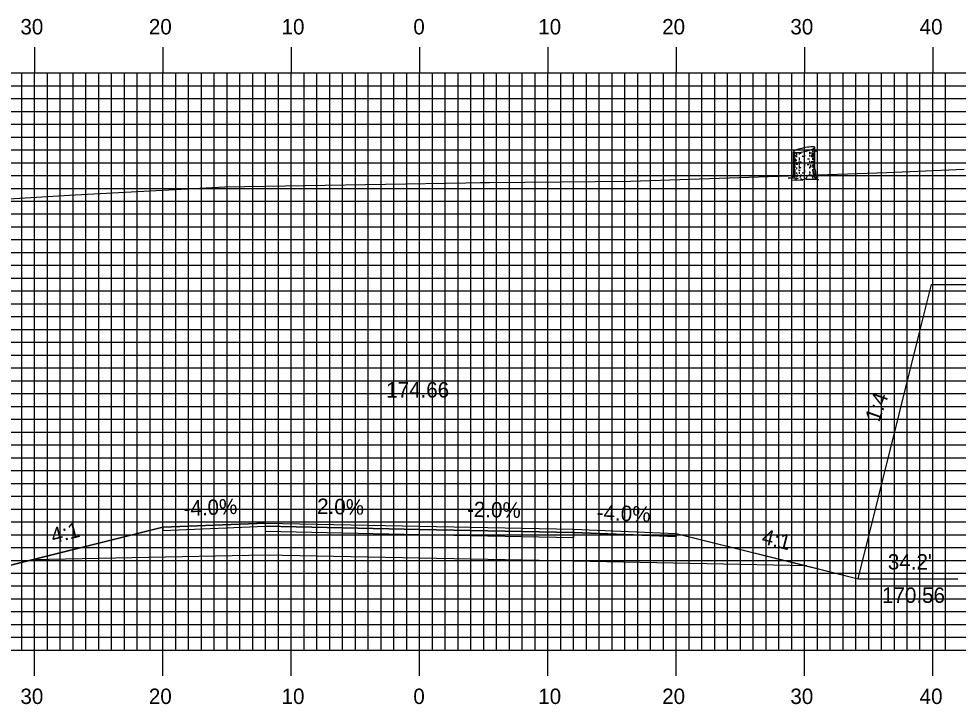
# Model space of a CAD drawing. Extents: x 1795240 to 1795583, y 442591 to 442811.
# Drawn here: x 1795374.1 to 1795447.3, y 442679.4 to 442732.9 of the extents above; entities that cross this region are included whole.
import ezdxf

# ---------------------------------------------------------------- set-up
doc = ezdxf.new("R2010")
doc.units = 0
for name, color, linetype in [('ANNOTATION', 7, 'Continuous'), ('D_Roadway_Centerline', 7, 'Continuous'), ('D_Roadway_Centerline_Text', 7, 'Continuous'), ('D_Roadway_Edge_Shoulder', 7, 'Continuous'), ('D_Roadway_Edge_TW', 7, 'Continuous'), ('D_Roadway_Pavement', 7, 'Continuous'), ('D_Roadway_SlopeLines', 7, 'Continuous'), ('D_Roadway_SubGrade', 7, 'Continuous'), ('H_V ANNOTATION', 7, 'Continuous'), ('M_Trees_Conifer_Pay', 7, 'Continuous'), ('MAJOR', 7, 'Continuous'), ('MINOR', 7, 'Continuous'), ('PDRAIN', 7, 'Continuous'), ('S_Roadway_Centerline', 7, 'Continuous')]:
    doc.layers.add(name, color=color, linetype=linetype)

msp = doc.modelspace()

# ---------------------------------------------------------------- linework, layer by layer
at = {"layer": 'D_Roadway_Centerline'}
msp.add_lwpolyline([(1795337.256, 442715.538), (1795361.802, 442703.265), (1795367.802, 442703.265), (1795371.192, 442689.704), (1795375.192, 442690.704), (1795385.366, 442693.248), (1795393.366, 442693.568), (1795405.366, 442693.328), (1795417.366, 442693.088), (1795425.366, 442692.768), (1795435.54, 442690.224), (1795439.54, 442689.224), (1795444.366, 442708.528)], dxfattribs=at)
at = {"layer": 'D_Roadway_Edge_Shoulder'}
for points in [[(1795393.366, 442693.568), (1795385.366, 442693.248), (1795385.366, 442692.998), (1795393.366, 442693.318)], [(1795417.366, 442693.088), (1795425.366, 442692.768), (1795425.366, 442692.518), (1795417.366, 442692.838)]]:
    msp.add_lwpolyline(points, close=True, dxfattribs=at)
at = {"layer": 'D_Roadway_Edge_TW'}
msp.add_lwpolyline([(1795393.366, 442693.318), (1795393.366, 442693.568), (1795405.366, 442693.328), (1795417.366, 442693.088), (1795417.366, 442692.838), (1795405.366, 442693.078)], close=True, dxfattribs=at)
at = {"layer": 'D_Roadway_Pavement'}
msp.add_lwpolyline([(1795393.366, 442692.901), (1795393.366, 442693.318), (1795405.366, 442693.078), (1795417.366, 442692.838), (1795417.366, 442692.421), (1795405.366, 442692.661)], close=True, dxfattribs=at)
at = {"layer": 'D_Roadway_SlopeLines'}
for points in [[(1795444.366, 442708.528), (1795445.275, 442712.165), (1795451.275, 442712.165)], [(1795385.366, 442693.248), (1795371.192, 442689.704)], [(1795425.366, 442692.768), (1795439.54, 442689.224)]]:
    msp.add_lwpolyline(points, dxfattribs=at)
at = {"layer": 'D_Roadway_SubGrade'}
msp.add_lwpolyline([(1795393.366, 442691.068), (1795375.192, 442690.704), (1795385.366, 442693.248), (1795385.366, 442692.998), (1795393.366, 442693.318), (1795405.366, 442693.078), (1795417.366, 442692.838), (1795425.366, 442692.518), (1795425.366, 442692.768), (1795435.54, 442690.224), (1795417.366, 442690.588), (1795405.366, 442690.828)], close=True, dxfattribs=at)
at = {"layer": 'M_Trees_Conifer_Pay'}
for p, q in [((1795434.504, 442720.788), (1795434.504, 442722.51)), ((1795434.551, 442722.472), (1795434.551, 442722.001)), ((1795434.609, 442722.461), (1795434.609, 442722.363)), ((1795434.609, 442722.289), (1795434.609, 442722.085)), ((1795434.735, 442722.453), (1795434.735, 442722.221)), ((1795434.735, 442722.18), (1795434.735, 442722.106)), ((1795434.954, 442722.474), (1795434.954, 442722.306)), ((1795435.36, 442722.242), (1795435.36, 442722.147)), ((1795435.75, 442722.516), (1795435.75, 442722.316)), ((1795435.75, 442722.258), (1795435.75, 442722.17)), ((1795435.979, 442722.712), (1795435.979, 442722.489)), ((1795435.979, 442722.4), (1795435.979, 442722.353)), ((1795436.036, 442722.217), (1795435.985, 442722.157)), ((1795436.096, 442722.773), (1795436.096, 442722.61)), ((1795436.096, 442722.542), (1795436.096, 442722.414)), ((1795436.096, 442722.227), (1795436.096, 442721.891)), ((1795436.168, 442721.198), (1795436.168, 442722.845)), ((1795434.551, 442721.937), (1795434.551, 442721.628)), ((1795434.551, 442721.581), (1795434.551, 442721.089)), ((1795434.609, 442722.027), (1795434.609, 442721.828)), ((1795434.609, 442721.781), (1795434.609, 442721.445)), ((1795434.735, 442721.703), (1795434.735, 442721.564)), ((1795434.954, 442722.069), (1795434.954, 442721.832)), ((1795434.954, 442721.587), (1795434.954, 442721.435)), ((1795435.36, 442721.628), (1795435.36, 442721.554)), ((1795435.36, 442721.529), (1795435.36, 442721.381)), ((1795435.75, 442721.822), (1795435.75, 442721.717)), ((1795435.979, 442722.017), (1795435.979, 442721.886)), ((1795435.979, 442721.775), (1795435.979, 442721.665)), ((1795435.979, 442721.529), (1795435.979, 442721.388)), ((1795436.096, 442721.855), (1795436.096, 442721.692)), ((1795436.096, 442721.645), (1795436.096, 442721.428)), ((1795434.551, 442721.035), (1795434.551, 442720.788)), ((1795434.609, 442721.391), (1795434.609, 442721.256)), ((1795434.609, 442721.157), (1795434.609, 442720.778)), ((1795434.735, 442721.292), (1795434.735, 442721.151)), ((1795434.735, 442720.889), (1795434.735, 442720.794)), ((1795434.954, 442721.391), (1795434.954, 442721.218)), ((1795434.954, 442720.941), (1795434.954, 442720.788)), ((1795435.36, 442721.089), (1795435.36, 442720.936)), ((1795435.75, 442721.35), (1795435.75, 442721.204)), ((1795435.75, 442720.972), (1795435.75, 442720.883)), ((1795435.979, 442721.161), (1795435.979, 442720.988)), ((1795436.096, 442721.397), (1795436.096, 442721.323)), ((1795436.096, 442721.283), (1795436.096, 442721.109)), ((1795434.735, 442720.395), (1795434.897, 442720.458)), ((1795435.172, 442720.33), (1795435.046, 442720.395))]:
    msp.add_line(p, q, dxfattribs=at)
for points in [[(1795435.951, 442722.306), (1795435.92, 442722.221), (1795435.916, 442722.153), (1795435.947, 442722.09)], [(1795435.985, 442722.343), (1795436.021, 442722.269), (1795436.069, 442722.326), (1795436.126, 442722.394), (1795436.219, 442722.588), (1795436.283, 442722.635), (1795436.314, 442722.641)], [(1795435.999, 442722.09), (1795436.036, 442722.217), (1795436.099, 442722.332), (1795436.13, 442722.4), (1795436.199, 442722.546)], [(1795436.214, 442722.576), (1795436.289, 442722.584), (1795436.361, 442722.485)], [(1795434.683, 442721.815), (1795434.677, 442721.911), (1795434.72, 442721.888), (1795434.72, 442721.793)], [(1795435.822, 442721.416), (1795435.834, 442721.34), (1795435.882, 442721.35), (1795435.869, 442721.517)], [(1795436.168, 442721.198), (1795436.219, 442720.936), (1795436.235, 442720.662), (1795436.293, 442720.537), (1795436.429, 442720.506), (1795436.198, 442720.469), (1795436.198, 442720.469), (1795436.204, 442720.422), (1795436.452, 442720.327), (1795436.177, 442720.344), (1795435.822, 442720.364), (1795435.5, 442720.353), (1795435.507, 442720.436), (1795435.359, 442720.353), (1795435.172, 442720.33), (1795435.196, 442720.263), (1795434.928, 442720.306), (1795434.708, 442720.279), (1795434.415, 442720.296), (1795434.704, 442720.353), (1795434.735, 442720.395), (1795434.572, 442720.453), (1795434.335, 442720.463), (1795434.094, 442720.463), (1795434.436, 442720.521), (1795434.477, 442720.601), (1795434.504, 442720.788)], [(1795434.551, 442720.741), (1795434.53, 442720.662), (1795434.51, 442720.568)], [(1795434.63, 442720.72), (1795434.635, 442720.605), (1795434.582, 442720.516), (1795434.572, 442720.453)], [(1795434.792, 442720.747), (1795434.792, 442720.615), (1795434.704, 442720.516)], [(1795435.019, 442720.506), (1795435.086, 442720.601), (1795435.113, 442720.741)], [(1795435.758, 442720.805), (1795435.768, 442720.679), (1795435.842, 442720.636)], [(1795435.994, 442720.91), (1795436.069, 442720.805), (1795436.073, 442720.632), (1795436.198, 442720.469)], [(1795436.093, 442721.056), (1795436.099, 442720.91), (1795436.147, 442720.842), (1795436.157, 442720.642)], [(1795435.507, 442720.436), (1795435.581, 442720.578), (1795435.591, 442720.679)], [(1795436.036, 442720.416), (1795436.021, 442720.554), (1795435.947, 442720.683)]]:
    msp.add_lwpolyline(points, dxfattribs=at)
for centre, radius, start, end in [((1795434.536, 442722.331), 0.0334, 163.94846, 180), ((1795434.536, 442722.331), 0.0334, 180, 196.05154), ((1795434.535, 442722.508), 0.0314, 156.51582, 169.2194), ((1795434.53, 442722.509), 0.0264, 169.2194, 180.03145), ((1795434.526, 442722.509), 0.0226, 180.03145, 191.7194), ((1795434.526, 442722.509), 0.0226, 191.7194, 203.40735), ((1795434.546, 442722.334), 0.0441, 196.05154, 210), ((1795434.555, 442722.5), 0.0527, 146.7194, 156.51582), ((1795434.53, 442722.511), 0.0264, 203.40735, 214.2194), ((1795434.534, 442722.514), 0.0314, 214.2194, 226.92298), ((1795434.562, 442722.343), 0.0624, 210, 228.74941), ((1795434.579, 442722.484), 0.0817, 132.38868, 146.7194), ((1795434.548, 442722.529), 0.0527, 226.92298, 236.7194), ((1795434.564, 442722.553), 0.0817, 236.7194, 251.05013), ((1795434.634, 442722.426), 0.172, 228.74941, 240), ((1795434.693, 442722.359), 0.251, 124.2194, 132.38868), ((1795434.619, 442722.713), 0.251, 251.05013, 259.2194), ((1795434.834, 442722.771), 0.571, 240, 240.33672), ((1795435.003, 442721.904), 0.802, 108.05939, 124.2194), ((1795434.722, 442723.254), 0.802, 259.2194, 275.37941), ((1795434.834, 442722.771), 0.571, 246.85973, 257.98457), ((1795436.359, 442717.742), 5.179, 101.7194, 108.05939), ((1795434.312, 442727.612), 5.179, 275.37941, 281.7194), ((1795435.336, 442726.522), 4.124, 264.6955, 266.73309), ((1795436.359, 442717.742), 5.179, 95.37941, 101.7194), ((1795434.312, 442727.612), 5.179, 281.7194, 288.05939), ((1795435.334, 442726.289), 4.124, 275.78493, 277.05584), ((1795435.336, 442726.522), 4.124, 276.23804, 278.1032), ((1795435.949, 442722.1), 0.802, 79.2194, 95.37941), ((1795435.669, 442723.451), 0.802, 288.05939, 304.2194), ((1795435.837, 442723.004), 0.571, 278.1032, 284.36665), ((1795435.837, 442723.158), 0.571, 284.43166, 292.41325), ((1795435.837, 442723.004), 0.571, 297.0237, 300), ((1795436.052, 442722.641), 0.251, 71.05013, 79.2194), ((1795435.979, 442722.995), 0.251, 304.2194, 312.38868), ((1795436.036, 442722.813), 0.172, 300, 311.25059), ((1795436.036, 442722.659), 0.172, 300, 311.25059), ((1795436.107, 442722.801), 0.0817, 56.7194, 71.05013), ((1795436.093, 442722.87), 0.0817, 312.38868, 326.7194), ((1795436.108, 442722.731), 0.0624, 311.25059, 330), ((1795436.108, 442722.576), 0.0624, 311.25059, 330), ((1795436.123, 442722.825), 0.0527, 46.92298, 56.7194), ((1795436.137, 442722.841), 0.0314, 34.2194, 46.92298), ((1795436.117, 442722.855), 0.0527, 326.7194, 336.51582), ((1795436.124, 442722.722), 0.0441, 330, 343.94846), ((1795436.124, 442722.567), 0.0441, 330, 343.94846), ((1795436.142, 442722.844), 0.0264, 23.40735, 34.2194), ((1795436.136, 442722.846), 0.0314, 336.51582, 349.2194), ((1795436.145, 442722.845), 0.0226, 11.7194, 23.40735), ((1795436.145, 442722.845), 0.0226, 0.03145, 11.7194), ((1795436.141, 442722.845), 0.0264, 349.2194, 0.03145), ((1795436.135, 442722.719), 0.0334, 343.94846, 354.21506), ((1795436.135, 442722.564), 0.0334, 343.94846, 354.21506), ((1795434.536, 442721.885), 0.0334, 163.94846, 180), ((1795434.536, 442721.885), 0.0334, 180, 196.05154), ((1795434.536, 442721.675), 0.0334, 163.94846, 180), ((1795434.536, 442721.675), 0.0334, 180, 196.05154), ((1795434.546, 442721.888), 0.0441, 196.05154, 210), ((1795434.546, 442721.677), 0.0441, 196.05154, 210), ((1795434.562, 442721.897), 0.0624, 210, 228.74941), ((1795434.562, 442721.687), 0.0624, 210, 228.74941), ((1795434.634, 442721.979), 0.172, 228.74941, 240), ((1795434.634, 442721.769), 0.172, 228.74941, 240), ((1795434.834, 442722.324), 0.571, 240, 240.33672), ((1795434.834, 442722.114), 0.571, 240, 246.85973), ((1795434.835, 442722.56), 0.571, 240, 247.05866), ((1795434.834, 442722.114), 0.571, 259.27072, 261.8968), ((1795435.334, 442725.632), 4.124, 261.8968, 263.14738), ((1795435.334, 442725.842), 4.124, 264.08098, 266.66759), ((1795435.334, 442726.289), 4.124, 268.07512, 270), ((1795435.334, 442726.289), 4.124, 270, 270.35814), ((1795435.334, 442725.632), 4.124, 270, 270.35814), ((1795435.334, 442725.632), 4.124, 273.14934, 275.45691), ((1795435.336, 442726.078), 4.124, 273.70524, 275.95043), ((1795435.334, 442725.842), 4.124, 277.61247, 278.1032), ((1795435.835, 442722.324), 0.571, 278.1032, 286.92962), ((1795435.837, 442722.56), 0.571, 284.44928, 297.04285), ((1795435.835, 442722.324), 0.571, 297.18959, 300), ((1795435.835, 442722.114), 0.571, 297.18959, 300), ((1795436.034, 442721.979), 0.172, 300, 311.25059), ((1795436.034, 442721.769), 0.172, 300, 311.25059), ((1795436.107, 442721.897), 0.0624, 311.25059, 330), ((1795436.107, 442721.687), 0.0624, 311.25059, 330), ((1795436.123, 442721.888), 0.0441, 330, 343.94846), ((1795436.123, 442721.677), 0.0441, 330, 343.94846), ((1795436.133, 442721.885), 0.0334, 343.94846, 354.21506), ((1795436.133, 442721.675), 0.0334, 343.94846, 354.21506), ((1795436.134, 442722.12), 0.0334, 343.94846, 354.21506), ((1795434.536, 442721.438), 0.0334, 163.94846, 180), ((1795434.536, 442721.438), 0.0334, 180, 196.05154), ((1795434.536, 442721.24), 0.0334, 163.94846, 180), ((1795434.536, 442721.044), 0.0334, 163.94846, 180), ((1795434.536, 442721.044), 0.0334, 180, 196.05154), ((1795434.536, 442720.824), 0.0334, 163.94846, 180), ((1795434.536, 442720.824), 0.0334, 180, 196.05154), ((1795434.546, 442721.441), 0.0441, 196.05154, 210), ((1795434.546, 442721.047), 0.0441, 196.05154, 210), ((1795434.546, 442720.827), 0.0441, 196.05154, 210), ((1795434.562, 442721.45), 0.0624, 210, 228.74941), ((1795434.562, 442721.057), 0.0624, 210, 228.74941), ((1795434.562, 442720.836), 0.0624, 210, 228.74941), ((1795434.634, 442721.532), 0.172, 228.74941, 240), ((1795434.634, 442721.139), 0.172, 228.74941, 240), ((1795434.634, 442720.919), 0.172, 228.74941, 240), ((1795434.834, 442721.878), 0.571, 240, 246.85973), ((1795434.823, 442721.686), 0.571, 241.23686, 248.02677), ((1795434.834, 442721.484), 0.571, 240, 246.85973), ((1795434.834, 442721.264), 0.571, 240, 244.53138), ((1795435.334, 442725.197), 4.124, 263.49906, 265.83975), ((1795435.334, 442725.395), 4.124, 264.71603, 266.31934), ((1795435.334, 442725.002), 4.124, 267.81166, 270), ((1795435.334, 442725.002), 4.124, 270, 270.13279), ((1795435.334, 442725.002), 4.124, 275.78493, 276.78961), ((1795435.835, 442721.878), 0.571, 285.39827, 297.18959), ((1795435.835, 442721.484), 0.571, 288.50673, 297.27208), ((1795435.835, 442721.68), 0.571, 289.29072, 300), ((1795436.034, 442721.335), 0.172, 300, 311.25059), ((1795436.034, 442720.919), 0.172, 300, 311.25059), ((1795436.107, 442721.252), 0.0624, 311.25059, 330), ((1795436.107, 442720.836), 0.0624, 311.25059, 330), ((1795436.123, 442721.243), 0.0441, 330, 343.94846), ((1795436.123, 442720.827), 0.0441, 330, 343.94846), ((1795436.133, 442721.24), 0.0334, 343.94846, 354.21506), ((1795436.133, 442720.824), 0.0334, 343.94846, 354.21506), ((1795435.334, 442724.781), 4.124, 262.44379, 263.51202), ((1795435.334, 442724.781), 4.124, 277.36842, 278.1032), ((1795435.835, 442721.264), 0.571, 278.1032, 281.63703)]:
    msp.add_arc(centre, radius, start, end, dxfattribs=at)
at = {"layer": 'MAJOR'}
for p, q in [((1795375.366, 442730.669), (1795375.366, 442728.665)), ((1795385.366, 442730.669), (1795385.366, 442728.665)), ((1795395.366, 442730.669), (1795395.366, 442728.665)), ((1795405.366, 442730.669), (1795405.366, 442728.665)), ((1795415.366, 442730.669), (1795415.366, 442728.665)), ((1795425.366, 442730.669), (1795425.366, 442728.665)), ((1795435.366, 442730.669), (1795435.366, 442728.665)), ((1795445.366, 442730.669), (1795445.366, 442728.665)), ((1795265.366, 442728.665), (1795545.366, 442728.665)), ((1795265.366, 442728.665), (1795545.366, 442728.665)), ((1795375.366, 442683.665), (1795375.366, 442728.665)), ((1795385.366, 442683.665), (1795385.366, 442728.665)), ((1795395.366, 442683.665), (1795395.366, 442728.665)), ((1795405.366, 442683.665), (1795405.366, 442728.665)), ((1795415.366, 442683.665), (1795415.366, 442728.665)), ((1795425.366, 442683.665), (1795425.366, 442728.665)), ((1795435.366, 442683.665), (1795435.366, 442728.665)), ((1795445.366, 442683.665), (1795445.366, 442728.665)), ((1795265.366, 442723.665), (1795545.366, 442723.665)), ((1795265.366, 442718.665), (1795545.366, 442718.665)), ((1795265.366, 442713.665), (1795545.366, 442713.665)), ((1795265.366, 442708.665), (1795545.366, 442708.665)), ((1795265.366, 442703.665), (1795545.366, 442703.665)), ((1795265.366, 442698.665), (1795545.366, 442698.665)), ((1795265.366, 442693.665), (1795545.366, 442693.665)), ((1795265.366, 442688.665), (1795545.366, 442688.665)), ((1795265.366, 442683.665), (1795545.366, 442683.665)), ((1795265.366, 442683.665), (1795545.366, 442683.665)), ((1795375.366, 442681.661), (1795375.366, 442683.665)), ((1795385.366, 442681.661), (1795385.366, 442683.665)), ((1795395.366, 442681.661), (1795395.366, 442683.665)), ((1795405.366, 442681.661), (1795405.366, 442683.665)), ((1795415.366, 442681.661), (1795415.366, 442683.665)), ((1795425.366, 442681.661), (1795425.366, 442683.665)), ((1795435.366, 442681.661), (1795435.366, 442683.665)), ((1795445.366, 442681.661), (1795445.366, 442683.665))]:
    msp.add_line(p, q, dxfattribs=at)
at = {"layer": 'MINOR'}
for p, q in [((1795374.366, 442683.665), (1795374.366, 442728.665)), ((1795376.366, 442683.665), (1795376.366, 442728.665)), ((1795377.366, 442683.665), (1795377.366, 442728.665)), ((1795378.366, 442683.665), (1795378.366, 442728.665)), ((1795379.366, 442683.665), (1795379.366, 442728.665)), ((1795380.366, 442683.665), (1795380.366, 442728.665)), ((1795381.366, 442683.665), (1795381.366, 442728.665)), ((1795382.366, 442683.665), (1795382.366, 442728.665)), ((1795383.366, 442683.665), (1795383.366, 442728.665)), ((1795384.366, 442683.665), (1795384.366, 442728.665)), ((1795386.366, 442683.665), (1795386.366, 442728.665)), ((1795387.366, 442683.665), (1795387.366, 442728.665)), ((1795388.366, 442683.665), (1795388.366, 442728.665)), ((1795389.366, 442683.665), (1795389.366, 442728.665)), ((1795390.366, 442683.665), (1795390.366, 442728.665)), ((1795391.366, 442683.665), (1795391.366, 442728.665)), ((1795392.366, 442683.665), (1795392.366, 442728.665)), ((1795393.366, 442683.665), (1795393.366, 442728.665)), ((1795394.366, 442683.665), (1795394.366, 442728.665)), ((1795396.366, 442683.665), (1795396.366, 442728.665)), ((1795397.366, 442683.665), (1795397.366, 442728.665)), ((1795398.366, 442683.665), (1795398.366, 442728.665)), ((1795399.366, 442683.665), (1795399.366, 442728.665)), ((1795400.366, 442683.665), (1795400.366, 442728.665)), ((1795401.366, 442683.665), (1795401.366, 442728.665)), ((1795402.366, 442683.665), (1795402.366, 442728.665)), ((1795403.366, 442683.665), (1795403.366, 442728.665)), ((1795404.366, 442683.665), (1795404.366, 442728.665)), ((1795406.366, 442683.665), (1795406.366, 442728.665)), ((1795407.366, 442683.665), (1795407.366, 442728.665)), ((1795408.366, 442683.665), (1795408.366, 442728.665)), ((1795409.366, 442683.665), (1795409.366, 442728.665)), ((1795410.366, 442683.665), (1795410.366, 442728.665)), ((1795411.366, 442683.665), (1795411.366, 442728.665)), ((1795412.366, 442683.665), (1795412.366, 442728.665)), ((1795413.366, 442683.665), (1795413.366, 442728.665)), ((1795414.366, 442683.665), (1795414.366, 442728.665)), ((1795416.366, 442683.665), (1795416.366, 442728.665)), ((1795417.366, 442683.665), (1795417.366, 442728.665)), ((1795418.366, 442683.665), (1795418.366, 442728.665)), ((1795419.366, 442683.665), (1795419.366, 442728.665)), ((1795420.366, 442683.665), (1795420.366, 442728.665)), ((1795421.366, 442683.665), (1795421.366, 442728.665)), ((1795422.366, 442683.665), (1795422.366, 442728.665)), ((1795423.366, 442683.665), (1795423.366, 442728.665)), ((1795424.366, 442683.665), (1795424.366, 442728.665)), ((1795426.366, 442683.665), (1795426.366, 442728.665)), ((1795427.366, 442683.665), (1795427.366, 442728.665)), ((1795428.366, 442683.665), (1795428.366, 442728.665)), ((1795429.366, 442683.665), (1795429.366, 442728.665)), ((1795430.366, 442683.665), (1795430.366, 442728.665)), ((1795431.366, 442683.665), (1795431.366, 442728.665)), ((1795432.366, 442683.665), (1795432.366, 442728.665)), ((1795433.366, 442683.665), (1795433.366, 442728.665)), ((1795434.366, 442683.665), (1795434.366, 442728.665)), ((1795436.366, 442683.665), (1795436.366, 442728.665)), ((1795437.366, 442683.665), (1795437.366, 442728.665)), ((1795438.366, 442683.665), (1795438.366, 442728.665)), ((1795439.366, 442683.665), (1795439.366, 442728.665)), ((1795440.366, 442683.665), (1795440.366, 442728.665)), ((1795441.366, 442683.665), (1795441.366, 442728.665)), ((1795442.366, 442683.665), (1795442.366, 442728.665)), ((1795443.366, 442683.665), (1795443.366, 442728.665)), ((1795444.366, 442683.665), (1795444.366, 442728.665)), ((1795446.366, 442683.665), (1795446.366, 442728.665)), ((1795265.366, 442727.665), (1795545.366, 442727.665)), ((1795265.366, 442726.665), (1795545.366, 442726.665)), ((1795265.366, 442725.665), (1795545.366, 442725.665)), ((1795265.366, 442724.665), (1795545.366, 442724.665)), ((1795265.366, 442722.665), (1795545.366, 442722.665)), ((1795265.366, 442721.665), (1795545.366, 442721.665)), ((1795265.366, 442720.665), (1795545.366, 442720.665)), ((1795265.366, 442719.665), (1795545.366, 442719.665)), ((1795265.366, 442717.665), (1795545.366, 442717.665)), ((1795265.366, 442716.665), (1795545.366, 442716.665)), ((1795265.366, 442715.665), (1795545.366, 442715.665)), ((1795265.366, 442714.665), (1795545.366, 442714.665)), ((1795265.366, 442712.665), (1795545.366, 442712.665)), ((1795265.366, 442711.665), (1795545.366, 442711.665)), ((1795265.366, 442710.665), (1795545.366, 442710.665)), ((1795265.366, 442709.665), (1795545.366, 442709.665)), ((1795265.366, 442707.665), (1795545.366, 442707.665)), ((1795265.366, 442706.665), (1795545.366, 442706.665)), ((1795265.366, 442705.665), (1795545.366, 442705.665)), ((1795265.366, 442704.665), (1795545.366, 442704.665)), ((1795265.366, 442702.665), (1795545.366, 442702.665)), ((1795265.366, 442701.665), (1795545.366, 442701.665)), ((1795265.366, 442700.665), (1795545.366, 442700.665)), ((1795265.366, 442699.665), (1795545.366, 442699.665)), ((1795265.366, 442697.665), (1795545.366, 442697.665)), ((1795265.366, 442696.665), (1795545.366, 442696.665)), ((1795265.366, 442695.665), (1795545.366, 442695.665)), ((1795265.366, 442694.665), (1795545.366, 442694.665)), ((1795265.366, 442692.665), (1795545.366, 442692.665)), ((1795265.366, 442691.665), (1795545.366, 442691.665)), ((1795265.366, 442690.665), (1795545.366, 442690.665)), ((1795265.366, 442689.665), (1795545.366, 442689.665)), ((1795265.366, 442687.665), (1795545.366, 442687.665)), ((1795265.366, 442686.665), (1795545.366, 442686.665)), ((1795265.366, 442685.665), (1795545.366, 442685.665)), ((1795265.366, 442684.665), (1795545.366, 442684.665))]:
    msp.add_line(p, q, dxfattribs=at)
at = {"layer": 'PDRAIN'}
msp.add_line((1795439.54, 442689.224), (1795447.321, 442689.224), dxfattribs=at)
at = {"layer": 'S_Roadway_Centerline'}
msp.add_lwpolyline([(1795332.201, 442716.579), (1795338.014, 442716.808), (1795347.079, 442717.285), (1795350.391, 442717.459), (1795360.026, 442718.049), (1795370.794, 442718.657), (1795373.791, 442718.875), (1795378.531, 442719.167), (1795390.189, 442719.781), (1795408.969, 442720.094), (1795410.097, 442720.113), (1795410.364, 442720.116), (1795410.815, 442720.127), (1795421.819, 442720.219), (1795441.788, 442720.912), (1795447.801, 442721.165)], dxfattribs=at)

# ---------------------------------------------------------------- texts
at = {"layer": 'ANNOTATION'}
for s, rotation, p in [('1:4', 70.51601, (1795441.176, 442701.38)), ('-4.0%', 2.29061, (1795386.998, 442694.114)), ('2.0%', 358.85424, (1795397.373, 442694.288)), ('-2.0%', 358.85424, (1795409.052, 442694.054)), ('-4.0%', 357.70939, (1795419.158, 442693.818)), ('4:1', 14.03624, (1795376.815, 442691.971)), ('4:1', 345.96376, (1795431.959, 442691.981))]:
    msp.add_text(s, height=1.2, rotation=rotation, dxfattribs=at).set_placement(p)
for s, p in [("34.2'", (1795441.861, 442689.95)), ('170.56', (1795441.405, 442687.35))]:
    msp.add_text(s, height=1.2, dxfattribs=at).set_placement(p)
at = {"layer": 'D_Roadway_Centerline'}
for s, p in [('C', (1795405.361, 442693.328)), ('L', (1795405.366, 442693.32))]:
    msp.add_text(s, height=0.0146, dxfattribs=at).set_placement(p)
at = {"layer": 'D_Roadway_Centerline_Text'}
msp.add_text('174.66', height=1.2, dxfattribs=at).set_placement((1795402.765, 442703.358))
at = {"layer": 'H_V ANNOTATION'}
for s, p in [('30', (1795374.263, 442731.665)), ('20', (1795384.274, 442731.665)), ('10', (1795394.617, 442731.665)), ('0', (1795404.884, 442731.665)), ('10', (1795414.617, 442731.665)), ('20', (1795424.274, 442731.665)), ('30', (1795434.263, 442731.665)), ('40', (1795444.338, 442731.665)), ('30', (1795374.263, 442679.465)), ('20', (1795384.274, 442679.465)), ('10', (1795394.617, 442679.465)), ('0', (1795404.884, 442679.465)), ('10', (1795414.617, 442679.465)), ('20', (1795424.274, 442679.465)), ('30', (1795434.263, 442679.465)), ('40', (1795444.338, 442679.465))]:
    msp.add_text(s, height=1.2, dxfattribs=at).set_placement(p)

doc.saveas('drawing.dxf')
